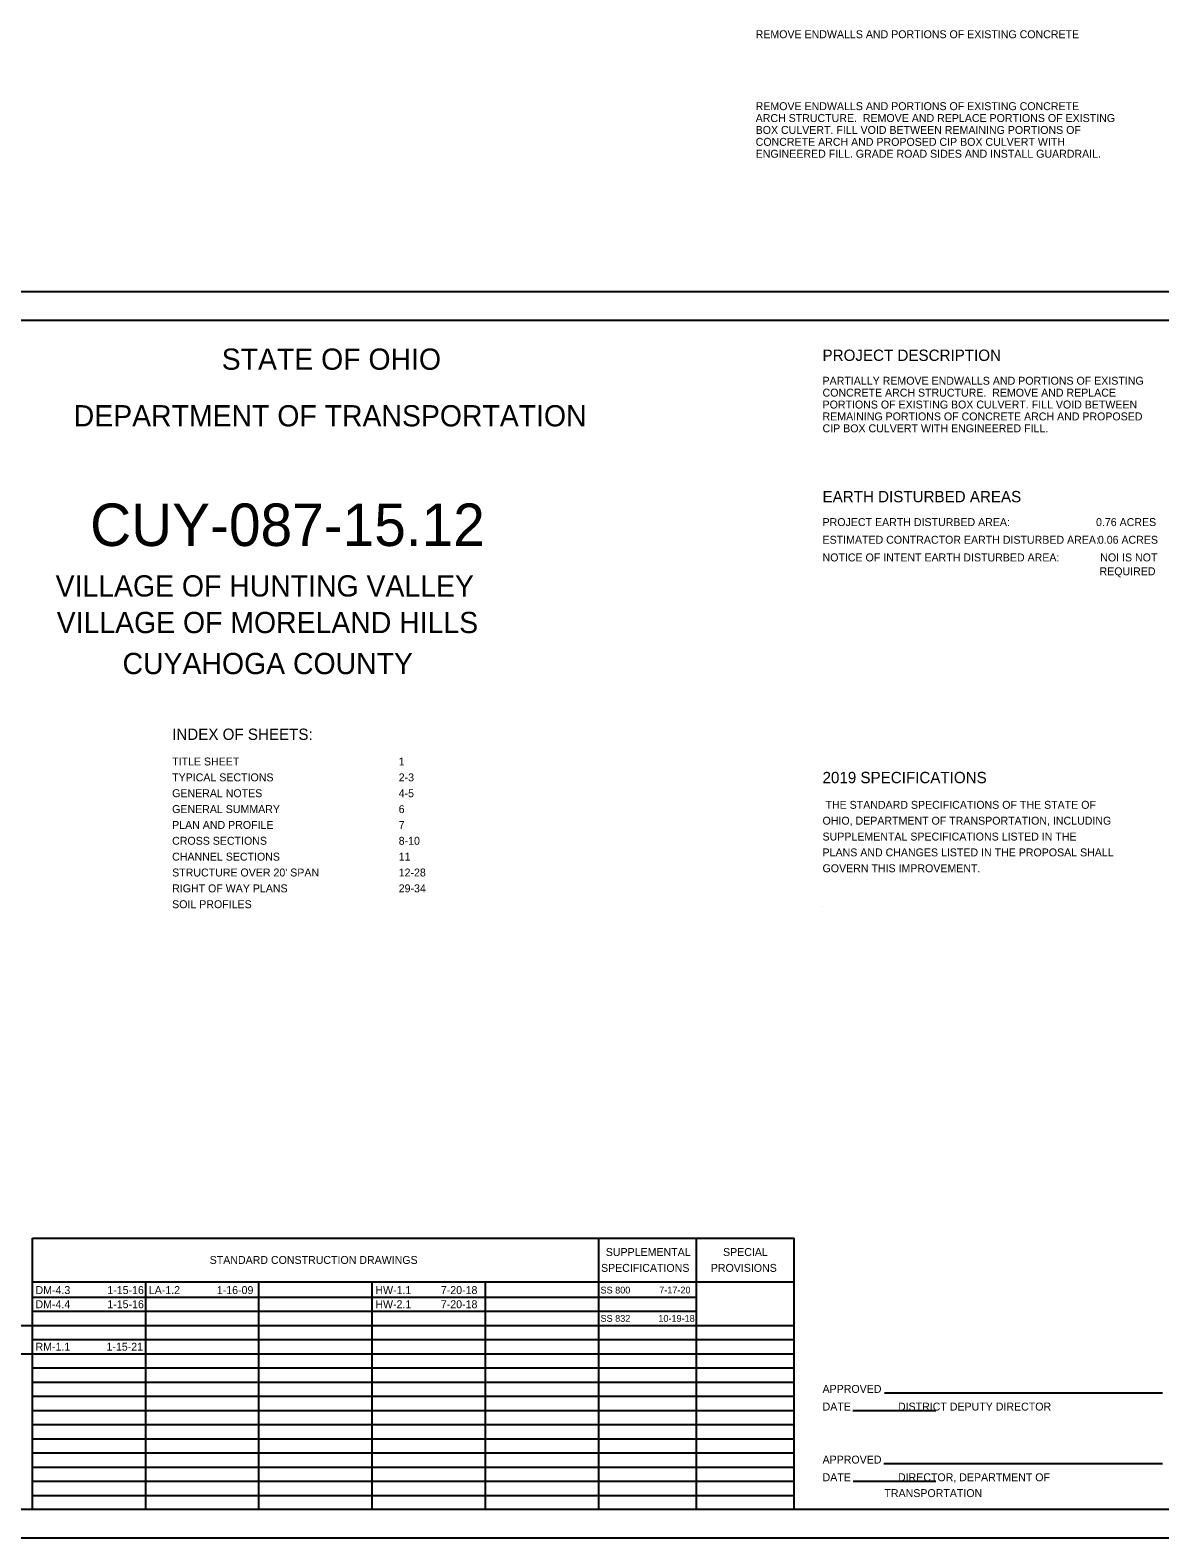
# Model space of a CAD drawing. Extents: x 421.3 to 469.3, y 221.6 to 248.2.
# Drawn here: x 433.32 to 453.26, y 221.63 to 248.25 of the extents above; entities that cross this region are included whole.
import ezdxf

# ---------------------------------------------------------------- set-up
doc = ezdxf.new("R2010")
doc.units = 0
for name, color, linetype in [('SH_Border', 7, 'Continuous'), ('SH_Cut_Line', 7, 'Continuous'), ('SH_Data', 7, 'Continuous')]:
    doc.layers.add(name, color=color, linetype=linetype)

msp = doc.modelspace()

# ---------------------------------------------------------------- linework, layer by layer
at = {"layer": 'SH_Border'}
msp.add_lwpolyline([(423.308, 243.128), (454.808, 243.128), (454.808, 222.128), (423.308, 222.128)], close=True, dxfattribs=at)
at = {"layer": 'SH_Cut_Line'}
msp.add_lwpolyline([(421.308, 221.628), (455.308, 221.628), (455.308, 243.628), (421.308, 243.628)], close=True, dxfattribs=at)
at = {"layer": 'SH_Data'}
for p, q in [((447.308, 232.769), (447.308, 232.769)), ((433.358, 226.92), (446.808, 226.92)), ((433.358, 222.128), (433.358, 226.92)), ((443.358, 222.128), (443.358, 226.92)), ((445.083, 222.128), (445.083, 226.92)), ((446.808, 222.128), (446.808, 226.92)), ((433.358, 226.149), (446.808, 226.149)), ((435.358, 222.128), (435.358, 226.149)), ((437.358, 222.128), (437.358, 226.149)), ((439.358, 222.128), (439.358, 226.149)), ((441.358, 222.128), (441.358, 226.149)), ((433.358, 225.878), (445.083, 225.878)), ((433.358, 225.628), (445.083, 225.628)), ((430.558, 225.378), (433.358, 225.378)), ((433.358, 225.378), (446.808, 225.378)), ((433.358, 225.128), (446.808, 225.128)), ((430.558, 224.878), (433.358, 224.878)), ((433.358, 224.878), (446.808, 224.878)), ((433.358, 224.628), (446.808, 224.628)), ((433.358, 224.378), (446.808, 224.378)), ((448.402, 224.188), (453.308, 224.188)), ((433.358, 224.128), (446.808, 224.128)), ((433.358, 223.878), (446.808, 223.878)), ((433.358, 223.628), (446.808, 223.628)), ((447.841, 223.876), (449.308, 223.876)), ((433.358, 223.378), (446.808, 223.378)), ((433.358, 223.128), (446.808, 223.128)), ((433.358, 222.878), (446.808, 222.878)), ((448.388, 222.94), (453.308, 222.94)), ((433.358, 222.628), (446.808, 222.628)), ((447.85, 222.628), (449.308, 222.628)), ((433.358, 222.378), (446.808, 222.378))]:
    msp.add_line(p, q, dxfattribs=at)

# ---------------------------------------------------------------- texts
for s, height, p in [('REMOVE ENDWALLS AND PORTIONS OF EXISTING CONCRETE', 0.14, (446.127, 248.107)), ('REMOVE ENDWALLS AND PORTIONS OF EXISTING CONCRETE', 0.14, (446.127, 246.837)), ('ARCH STRUCTURE.  REMOVE AND REPLACE PORTIONS OF EXISTING', 0.14, (446.127, 246.627)), ('BOX CULVERT. FILL VOID BETWEEN REMAINING PORTIONS OF', 0.14, (446.127, 246.417)), ('CONCRETE ARCH AND PROPOSED CIP BOX CULVERT WITH', 0.14, (446.127, 246.207)), ('ENGINEERED FILL. GRADE ROAD SIDES AND INSTALL GUARDRAIL. ', 0.14, (446.127, 245.997)), ('STATE OF OHIO', 0.375, (436.7, 242.253)), ('PROJECT DESCRIPTION', 0.2, (447.308, 242.409)), ('PARTIALLY REMOVE ENDWALLS AND PORTIONS OF EXISTING ', 0.14, (447.308, 241.989)), ('CONCRETE ARCH STRUCTURE.  REMOVE AND REPLACE ', 0.14, (447.308, 241.779)), ('DEPARTMENT OF TRANSPORTATION', 0.375, (434.088, 241.253)), ('PORTIONS OF EXISTING BOX CULVERT. FILL VOID BETWEEN ', 0.14, (447.308, 241.569)), ('REMAINING PORTIONS OF CONCRETE ARCH AND PROPOSED', 0.14, (447.308, 241.359)), ('CIP BOX CULVERT WITH ENGINEERED FILL. ', 0.14, (447.308, 241.149)), ('CUY-087-15.12', 0.75, (434.377, 239.141)), ('EARTH DISTURBED AREAS', 0.2, (447.308, 239.913)), ('PROJECT EARTH DISTURBED AREA:', 0.14, (447.308, 239.493)), (' 0.76 ACRES', 0.14, (452.084, 239.493)), ('ESTIMATED CONTRACTOR EARTH DISTURBED AREA:', 0.14, (447.308, 239.181)), ('0.06 ACRES', 0.14, (452.169, 239.181)), ('NOTICE OF INTENT EARTH DISTURBED AREA:', 0.14, (447.308, 238.869)), ('NOI IS NOT ', 0.14, (452.211, 238.869)), ('VILLAGE OF HUNTING VALLEY', 0.375, (433.768, 238.249)), ('REQUIRED ', 0.14, (452.198, 238.624)), ('VILLAGE OF MORELAND HILLS', 0.375, (433.787, 237.603)), ('  CUYAHOGA COUNTY  ', 0.375, (434.671, 236.879)), ('INDEX OF SHEETS:', 0.2, (435.825, 235.717)), ('TITLE SHEET                         ', 0.14, (435.825, 235.266)), ('1', 0.14, (439.825, 235.266)), ('TYPICAL SECTIONS                  ', 0.14, (435.825, 234.986)), ('2-3', 0.14, (439.825, 234.986)), ('2019 SPECIFICATIONS', 0.2, (447.308, 234.953)), ('GENERAL NOTES                     ', 0.14, (435.825, 234.706)), ('4-5', 0.14, (439.825, 234.706)), ('GENERAL SUMMARY                   ', 0.14, (435.825, 234.426)), ('6      ', 0.14, (439.825, 234.426)), (' THE STANDARD SPECIFICATIONS OF THE STATE OF', 0.14, (447.308, 234.501)), ('PLAN AND PROFILE                  ', 0.14, (435.825, 234.146)), ('7', 0.14, (439.825, 234.146)), ('OHIO, DEPARTMENT OF TRANSPORTATION, INCLUDING', 0.14, (447.308, 234.221)), ('CROSS SECTIONS                    ', 0.14, (435.825, 233.866)), ('8-10', 0.14, (439.825, 233.866)), ('SUPPLEMENTAL SPECIFICATIONS LISTED IN THE', 0.14, (447.308, 233.941)), ('PLANS AND CHANGES LISTED IN THE PROPOSAL SHALL', 0.14, (447.308, 233.661)), ('CHANNEL SECTIONS                  ', 0.14, (435.825, 233.586)), ('11', 0.14, (439.825, 233.586)), ('GOVERN THIS IMPROVEMENT.', 0.14, (447.308, 233.381)), ("STRUCTURE OVER 20' SPAN          ", 0.14, (435.825, 233.306)), ('12-28', 0.14, (439.825, 233.306)), ('RIGHT OF WAY PLANS', 0.14, (435.825, 233.026)), ('29-34', 0.14, (439.825, 233.026)), ('SOIL PROFILES', 0.14, (435.825, 232.746)), ('STANDARD CONSTRUCTION DRAWINGS', 0.14, (436.488, 226.465)), ('SUPPLEMENTAL', 0.14, (443.481, 226.605)), ('SPECIAL', 0.14, (445.551, 226.605)), ('SPECIFICATIONS', 0.14, (443.397, 226.325)), ('PROVISIONS', 0.14, (445.335, 226.325)), ('DM-4.3', 0.14, (433.413, 225.933)), ('1-15-16', 0.14, (434.681, 225.933)), ('LA-1.2', 0.14, (435.413, 225.933)), ('1-16-09', 0.14, (436.614, 225.933)), ('HW-1.1', 0.14, (439.413, 225.933)), ('7-20-18', 0.14, (440.569, 225.933)), ('SS 800', 0.12, (443.388, 225.943)), ('7-17-20', 0.12, (444.424, 225.943)), ('DM-4.4', 0.14, (433.413, 225.683)), ('1-15-16', 0.14, (434.681, 225.683)), ('HW-2.1', 0.14, (439.413, 225.683)), ('7-20-18', 0.14, (440.569, 225.683)), ('SS 832', 0.12, (443.388, 225.443)), ('10-19-18', 0.12, (444.409, 225.443)), ('RM-1.1', 0.14, (433.413, 224.933)), ('1-15-21', 0.14, (434.666, 224.933)), ('APPROVED', 0.14, (447.308, 224.188)), ('DATE                DISTRICT DEPUTY DIRECTOR', 0.14, (447.308, 223.876)), ('APPROVED', 0.14, (447.308, 222.94)), ('DATE                DIRECTOR, DEPARTMENT OF', 0.14, (447.308, 222.628)), ('                     TRANSPORTATION', 0.14, (447.308, 222.348))]:
    msp.add_text(s, height=height, dxfattribs=at).set_placement(p)

doc.saveas('drawing.dxf')
